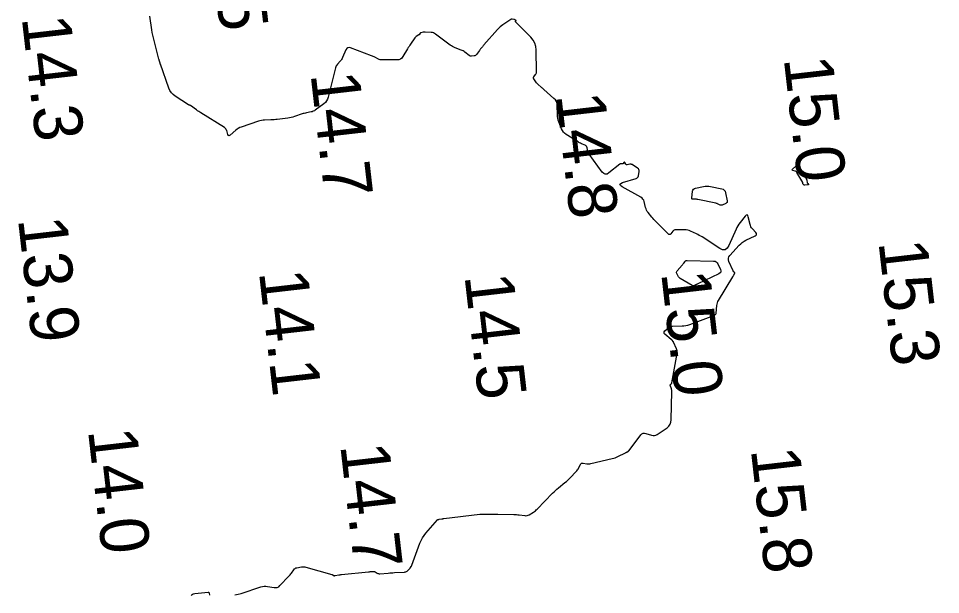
# Model space of a CAD drawing. Extents: x 1023796 to 1112670, y 656573 to 837340.
# Drawn here: x 1109831.6 to 1109926.4, y 680947.7 to 681006.9 of the extents above; entities that cross this region are included whole.
import ezdxf

# ---------------------------------------------------------------- set-up
doc = ezdxf.new("R2010")
doc.units = 0
doc.layers.add('V-CHAN-CONT-15FT', color=7, linetype='Continuous')
doc.layers.add('V-TOPO-SOUN', color=7, linetype='Continuous')

msp = doc.modelspace()

# ---------------------------------------------------------------- linework, layer by layer
at = {"layer": 'V-CHAN-CONT-15FT'}
for points in [[(1109853.897, 680947.649), (1109854.213, 680947.716), (1109854.525, 680947.805), (1109856.564, 680948.467), (1109856.731, 680948.51), (1109856.9, 680948.533), (1109857.07, 680948.536), (1109857.241, 680948.519), (1109857.931, 680948.407), (1109858.097, 680948.399), (1109858.25, 680948.429), (1109858.391, 680948.497), (1109858.518, 680948.604), (1109859.44, 680949.569), (1109859.511, 680949.646), (1109859.578, 680949.725), (1109859.641, 680949.808), (1109859.702, 680949.893), (1109859.936, 680950.239), (1109860, 680950.317), (1109860.075, 680950.378), (1109860.161, 680950.422), (1109860.258, 680950.449), (1109860.738, 680950.538), (1109860.851, 680950.552), (1109860.964, 680950.553), (1109861.077, 680950.541), (1109861.189, 680950.516), (1109863.848, 680949.753), (1109863.877, 680949.744), (1109863.905, 680949.733), (1109863.933, 680949.719), (1109863.959, 680949.704), (1109864.098, 680949.619), (1109864.107, 680949.615), (1109864.116, 680949.613), (1109864.125, 680949.613), (1109864.135, 680949.616), (1109864.173, 680949.632), (1109864.182, 680949.636), (1109864.192, 680949.639), (1109864.202, 680949.642), (1109864.212, 680949.644), (1109864.586, 680949.709), (1109864.652, 680949.719), (1109864.717, 680949.729), (1109864.784, 680949.738), (1109864.85, 680949.745), (1109867.625, 680950.027), (1109867.682, 680950.032), (1109867.738, 680950.038), (1109867.795, 680950.043), (1109867.852, 680950.049), (1109868.079, 680950.07), (1109868.134, 680950.071), (1109868.188, 680950.063), (1109868.24, 680950.047), (1109868.29, 680950.022), (1109868.528, 680949.882), (1109868.585, 680949.854), (1109868.644, 680949.835), (1109868.706, 680949.826), (1109868.77, 680949.827), (1109869.636, 680949.899), (1109869.802, 680949.913), (1109869.968, 680949.925), (1109870.134, 680949.936), (1109870.3, 680949.946), (1109871.337, 680950.004), (1109871.406, 680950.014), (1109871.47, 680950.034), (1109871.529, 680950.066), (1109871.584, 680950.108), (1109871.847, 680950.345), (1109871.873, 680950.37), (1109871.897, 680950.397), (1109871.919, 680950.426), (1109871.938, 680950.456), (1109872.014, 680950.58), (1109872.032, 680950.612), (1109872.048, 680950.644), (1109872.063, 680950.677), (1109872.077, 680950.711), (1109872.911, 680952.954), (1109873.03, 680953.236), (1109873.173, 680953.503), (1109873.34, 680953.757), (1109873.53, 680953.997), (1109874.721, 680955.37), (1109874.731, 680955.38), (1109874.743, 680955.389), (1109874.755, 680955.395), (1109874.769, 680955.4), (1109874.826, 680955.415), (1109874.841, 680955.418), (1109874.855, 680955.421), (1109874.87, 680955.424), (1109874.884, 680955.426), (1109875.158, 680955.466), (1109875.209, 680955.473), (1109875.259, 680955.48), (1109875.31, 680955.487), (1109875.36, 680955.493), (1109879.065, 680955.935), (1109879.142, 680955.943), (1109879.219, 680955.949), (1109879.296, 680955.952), (1109879.374, 680955.953), (1109879.683, 680955.951), (1109879.761, 680955.951), (1109879.838, 680955.951), (1109879.916, 680955.951), (1109879.993, 680955.952), (1109880.49, 680955.956), (1109880.598, 680955.957), (1109880.707, 680955.956), (1109880.816, 680955.955), (1109880.924, 680955.954), (1109882.566, 680955.921), (1109882.704, 680955.917), (1109882.841, 680955.908), (1109882.978, 680955.895), (1109883.115, 680955.878), (1109883.687, 680955.8), (1109883.808, 680955.793), (1109883.925, 680955.807), (1109884.039, 680955.841), (1109884.147, 680955.896), (1109884.574, 680956.155), (1109884.678, 680956.223), (1109884.778, 680956.297), (1109884.872, 680956.378), (1109884.961, 680956.465), (1109886.55, 680958.109), (1109886.694, 680958.253), (1109886.842, 680958.393), (1109886.995, 680958.528), (1109887.151, 680958.658), (1109887.817, 680959.195), (1109887.958, 680959.313), (1109888.096, 680959.435), (1109888.229, 680959.562), (1109888.359, 680959.693), (1109888.981, 680960.341), (1109889.05, 680960.418), (1109889.112, 680960.5), (1109889.168, 680960.586), (1109889.217, 680960.677), (1109889.407, 680961.06), (1109889.457, 680961.135), (1109889.521, 680961.183), (1109889.597, 680961.206), (1109889.688, 680961.202), (1109890.075, 680961.134), (1109890.172, 680961.122), (1109890.268, 680961.12), (1109890.364, 680961.127), (1109890.46, 680961.144), (1109892.67, 680961.654), (1109892.823, 680961.694), (1109892.974, 680961.743), (1109893.121, 680961.801), (1109893.264, 680961.867), (1109894.05, 680962.26), (1109894.084, 680962.277), (1109894.117, 680962.295), (1109894.15, 680962.314), (1109894.182, 680962.333), (1109894.311, 680962.41), (1109894.343, 680962.431), (1109894.371, 680962.454), (1109894.398, 680962.48), (1109894.421, 680962.509), (1109895.627, 680964.1), (1109895.73, 680964.205), (1109895.847, 680964.265), (1109895.977, 680964.282), (1109896.122, 680964.255), (1109896.727, 680964.058), (1109896.876, 680964.026), (1109897.02, 680964.029), (1109897.158, 680964.067), (1109897.292, 680964.14), (1109898.307, 680964.837), (1109898.493, 680964.998), (1109898.628, 680965.186), (1109898.711, 680965.402), (1109898.742, 680965.646), (1109898.801, 680968.565), (1109898.799, 680968.636), (1109898.79, 680968.706), (1109898.775, 680968.775), (1109898.753, 680968.842), (1109898.621, 680969.191), (1109898.615, 680969.216), (1109898.617, 680969.239), (1109898.628, 680969.259), (1109898.647, 680969.277), (1109898.738, 680969.343), (1109898.759, 680969.361), (1109898.775, 680969.382), (1109898.787, 680969.406), (1109898.794, 680969.432), (1109899.344, 680972.472), (1109899.357, 680972.596), (1109899.351, 680972.718), (1109899.327, 680972.837), (1109899.284, 680972.954), (1109898.973, 680973.636), (1109898.968, 680973.648), (1109898.963, 680973.661), (1109898.953, 680973.685), (1109898.95, 680973.691), (1109898.947, 680973.697), (1109898.944, 680973.702), (1109898.939, 680973.707), (1109898.825, 680973.834), (1109898.805, 680973.856), (1109898.783, 680973.877), (1109898.761, 680973.898), (1109898.737, 680973.918), (1109898.095, 680974.451), (1109898.023, 680974.531), (1109897.998, 680974.611), (1109898.019, 680974.693), (1109898.086, 680974.776), (1109898.447, 680975.111), (1109898.541, 680975.184), (1109898.643, 680975.237), (1109898.754, 680975.27), (1109898.873, 680975.283), (1109899.847, 680975.303), (1109900.049, 680975.316), (1109900.248, 680975.345), (1109900.444, 680975.39), (1109900.636, 680975.452), (1109902.848, 680976.268), (1109902.899, 680976.287), (1109902.95, 680976.309), (1109903, 680976.331), (1109903.05, 680976.355), (1109903.247, 680976.454), (1109903.291, 680976.482), (1109903.324, 680976.518), (1109903.346, 680976.561), (1109903.356, 680976.613), (1109903.431, 680977.379), (1109903.453, 680977.522), (1109903.491, 680977.661), (1109903.543, 680977.794), (1109903.611, 680977.922), (1109905.065, 680980.338), (1109905.09, 680980.38), (1109905.113, 680980.423), (1109905.136, 680980.467), (1109905.157, 680980.512), (1109905.261, 680980.743), (1109905.266, 680980.761), (1109905.265, 680980.777), (1109905.258, 680980.791), (1109905.244, 680980.803), (1109905.156, 680980.861), (1109905.149, 680980.867), (1109905.142, 680980.873), (1109905.136, 680980.881), (1109905.132, 680980.889), (1109905.111, 680980.933), (1109905.103, 680980.95), (1109905.099, 680980.959), (1109904.664, 680981.931), (1109904.614, 680982.093), (1109904.613, 680982.246), (1109904.662, 680982.391), (1109904.759, 680982.529), (1109905.721, 680983.591), (1109905.877, 680983.747), (1109906.046, 680983.886), (1109906.227, 680984.008), (1109906.421, 680984.112), (1109907.382, 680984.573), (1109907.476, 680984.636), (1109907.517, 680984.709), (1109907.506, 680984.792), (1109907.442, 680984.885), (1109907.081, 680985.279), (1109906.998, 680985.382), (1109906.93, 680985.492), (1109906.877, 680985.61), (1109906.839, 680985.736), (1109906.654, 680986.518), (1109906.604, 680986.653), (1109906.537, 680986.709), (1109906.452, 680986.686), (1109906.35, 680986.586), (1109905.822, 680985.916), (1109905.702, 680985.755), (1109905.594, 680985.587), (1109905.496, 680985.413), (1109905.408, 680985.232), (1109904.66, 680983.546), (1109904.487, 680983.272), (1109904.274, 680983.134), (1109904.02, 680983.132), (1109903.726, 680983.267), (1109901.908, 680984.437), (1109901.768, 680984.524), (1109901.625, 680984.607), (1109901.48, 680984.686), (1109901.332, 680984.76), (1109900.736, 680985.048), (1109900.585, 680985.111), (1109900.43, 680985.155), (1109900.27, 680985.181), (1109900.107, 680985.189), (1109899.185, 680985.181), (1109899.1, 680985.172), (1109899.024, 680985.145), (1109898.956, 680985.1), (1109898.898, 680985.037), (1109898.682, 680984.752), (1109898.627, 680984.698), (1109898.569, 680984.677), (1109898.509, 680984.69), (1109898.447, 680984.736), (1109897.146, 680986.032), (1109897.041, 680986.14), (1109896.939, 680986.25), (1109896.84, 680986.363), (1109896.744, 680986.479), (1109896.367, 680986.947), (1109896.28, 680987.068), (1109896.207, 680987.196), (1109896.149, 680987.331), (1109896.106, 680987.473), (1109895.958, 680988.071), (1109895.909, 680988.21), (1109895.836, 680988.331), (1109895.739, 680988.433), (1109895.619, 680988.518), (1109893.697, 680989.608), (1109893.52, 680989.737), (1109893.47, 680989.851), (1109893.545, 680989.951), (1109893.746, 680990.036), (1109895.119, 680990.44), (1109895.214, 680990.481), (1109895.288, 680990.542), (1109895.338, 680990.623), (1109895.367, 680990.723), (1109895.435, 680991.164), (1109895.438, 680991.268), (1109895.413, 680991.36), (1109895.362, 680991.439), (1109895.282, 680991.507), (1109894.727, 680991.871), (1109894.672, 680991.901), (1109894.615, 680991.918), (1109894.556, 680991.923), (1109894.495, 680991.916), (1109894.208, 680991.859), (1109894.166, 680991.856), (1109894.13, 680991.865), (1109894.098, 680991.885), (1109894.072, 680991.917), (1109893.963, 680992.087), (1109893.944, 680992.109), (1109893.925, 680992.117), (1109893.904, 680992.112), (1109893.883, 680992.094), (1109893.791, 680991.991), (1109893.77, 680991.971), (1109893.746, 680991.959), (1109893.719, 680991.952), (1109893.691, 680991.953), (1109893.57, 680991.967), (1109893.541, 680991.968), (1109893.513, 680991.963), (1109893.487, 680991.952), (1109893.463, 680991.936), (1109892.334, 680991.023), (1109892.143, 680990.91), (1109891.965, 680990.887), (1109891.798, 680990.954), (1109891.643, 680991.112), (1109890.295, 680992.948), (1109890.246, 680993.022), (1109890.207, 680993.1), (1109890.176, 680993.181), (1109890.154, 680993.267), (1109890.083, 680993.617), (1109890.058, 680993.698), (1109890.016, 680993.766), (1109889.958, 680993.821), (1109889.884, 680993.863), (1109889.505, 680994.027), (1109889.415, 680994.067), (1109889.327, 680994.111), (1109889.241, 680994.159), (1109889.157, 680994.21), (1109887.933, 680994.981), (1109887.781, 680995.094), (1109887.653, 680995.225), (1109887.547, 680995.377), (1109887.465, 680995.547), (1109887.184, 680996.267), (1109887.122, 680996.449), (1109887.077, 680996.634), (1109887.049, 680996.822), (1109887.038, 680997.013), (1109887.025, 680997.947), (1109887.001, 680998.157), (1109886.937, 680998.349), (1109886.832, 680998.522), (1109886.687, 680998.676), (1109885.637, 680999.591), (1109885.566, 680999.653), (1109885.496, 680999.716), (1109885.425, 680999.779), (1109885.355, 680999.842), (1109885.067, 681000.104), (1109885.003, 681000.165), (1109884.943, 681000.229), (1109884.886, 681000.296), (1109884.833, 681000.367), (1109884.608, 681000.685), (1109884.578, 681000.742), (1109884.569, 681000.798), (1109884.581, 681000.854), (1109884.615, 681000.909), (1109884.792, 681001.128), (1109884.83, 681001.184), (1109884.858, 681001.245), (1109884.874, 681001.309), (1109884.879, 681001.378), (1109884.862, 681003.656), (1109884.827, 681004.022), (1109884.725, 681004.362), (1109884.557, 681004.674), (1109884.324, 681004.959), (1109882.746, 681006.565), (1109882.738, 681006.576), (1109882.735, 681006.587), (1109882.737, 681006.598), (1109882.744, 681006.609), (1109882.781, 681006.655), (1109882.787, 681006.666), (1109882.788, 681006.677), (1109882.784, 681006.686), (1109882.774, 681006.694), (1109882.66, 681006.763), (1109882.636, 681006.776), (1109882.612, 681006.786), (1109882.586, 681006.794), (1109882.56, 681006.8), (1109882.381, 681006.826), (1109882.343, 681006.829), (1109882.306, 681006.824), (1109882.271, 681006.812), (1109882.238, 681006.794), (1109881.42, 681006.238), (1109881.277, 681006.134), (1109881.141, 681006.021), (1109881.013, 681005.9), (1109880.892, 681005.77), (1109879.493, 681004.17), (1109879.453, 681004.125), (1109879.413, 681004.079), (1109879.373, 681004.034), (1109879.333, 681003.988), (1109879.173, 681003.807), (1109879.133, 681003.761), (1109879.095, 681003.715), (1109879.058, 681003.667), (1109879.023, 681003.618), (1109878.711, 681003.183), (1109878.667, 681003.132), (1109878.616, 681003.093), (1109878.557, 681003.066), (1109878.491, 681003.051), (1109878.214, 681003.014), (1109878.146, 681003.012), (1109878.082, 681003.022), (1109878.022, 681003.046), (1109877.966, 681003.083), (1109877.537, 681003.426), (1109877.445, 681003.493), (1109877.349, 681003.553), (1109877.248, 681003.606), (1109877.143, 681003.65), (1109876.531, 681003.88), (1109876.396, 681003.937), (1109876.266, 681004.003), (1109876.141, 681004.077), (1109876.02, 681004.161), (1109874.509, 681005.299), (1109874.408, 681005.364), (1109874.302, 681005.412), (1109874.189, 681005.444), (1109874.07, 681005.458), (1109873.435, 681005.491), (1109873.387, 681005.492), (1109873.339, 681005.49), (1109873.291, 681005.485), (1109873.243, 681005.478), (1109873.016, 681005.434), (1109872.988, 681005.426), (1109872.964, 681005.413), (1109872.944, 681005.395), (1109872.927, 681005.373), (1109872.839, 681005.229), (1109872.837, 681005.226), (1109872.833, 681005.224), (1109872.829, 681005.223), (1109872.825, 681005.223), (1109872.807, 681005.226), (1109872.802, 681005.226), (1109872.798, 681005.225), (1109872.794, 681005.224), (1109872.79, 681005.222), (1109872.525, 681005.048), (1109872.482, 681005.016), (1109872.442, 681004.981), (1109872.406, 681004.942), (1109872.373, 681004.899), (1109871.945, 681004.267), (1109871.864, 681004.146), (1109871.786, 681004.024), (1109871.708, 681003.901), (1109871.633, 681003.776), (1109871.155, 681002.976), (1109871.038, 681002.823), (1109870.896, 681002.714), (1109870.73, 681002.65), (1109870.539, 681002.629), (1109869.004, 681002.639), (1109868.908, 681002.645), (1109868.814, 681002.662), (1109868.723, 681002.689), (1109868.635, 681002.728), (1109868.287, 681002.903), (1109868.199, 681002.946), (1109868.11, 681002.986), (1109868.02, 681003.024), (1109867.93, 681003.059), (1109865.776, 681003.863), (1109865.621, 681003.897), (1109865.489, 681003.875), (1109865.383, 681003.795), (1109865.3, 681003.659), (1109864.964, 681002.877), (1109864.916, 681002.778), (1109864.86, 681002.684), (1109864.796, 681002.595), (1109864.724, 681002.511), (1109864.421, 681002.187), (1109864.351, 681002.103), (1109864.294, 681002.012), (1109864.249, 681001.914), (1109864.216, 681001.81), (1109863.487, 680998.805), (1109863.419, 680998.601), (1109863.319, 680998.418), (1109863.189, 680998.256), (1109863.027, 680998.115), (1109862.153, 680997.473), (1109862.054, 680997.408), (1109861.949, 680997.356), (1109861.839, 680997.315), (1109861.724, 680997.287), (1109861.252, 680997.199), (1109861.135, 680997.175), (1109861.019, 680997.146), (1109860.903, 680997.114), (1109860.789, 680997.078), (1109860.022, 680996.817), (1109859.855, 680996.765), (1109859.686, 680996.721), (1109859.515, 680996.686), (1109859.343, 680996.66), (1109858.25, 680996.522), (1109858.088, 680996.503), (1109857.925, 680996.488), (1109857.762, 680996.476), (1109857.599, 680996.468), (1109856.946, 680996.442), (1109856.784, 680996.43), (1109856.623, 680996.406), (1109856.465, 680996.371), (1109856.309, 680996.325), (1109854.533, 680995.734), (1109854.382, 680995.676), (1109854.239, 680995.603), (1109854.105, 680995.515), (1109853.978, 680995.414), (1109853.404, 680994.903), (1109853.33, 680994.854), (1109853.268, 680994.848), (1109853.218, 680994.885), (1109853.179, 680994.964), (1109853.048, 680995.368), (1109853.008, 680995.463), (1109852.954, 680995.548), (1109852.886, 680995.621), (1109852.803, 680995.683), (1109850.398, 680997.199), (1109850.284, 680997.271), (1109850.172, 680997.345), (1109850.06, 680997.42), (1109849.949, 680997.497), (1109849.317, 680997.937), (1109849.302, 680997.947), (1109849.286, 680997.956), (1109849.269, 680997.963), (1109849.251, 680997.969), (1109849.18, 680997.99), (1109849.163, 680997.996), (1109849.146, 680998.003), (1109849.129, 680998.011), (1109849.114, 680998.021), (1109847.753, 680998.908), (1109847.539, 680999.073), (1109847.359, 680999.265), (1109847.214, 680999.484), (1109847.103, 680999.731), (1109846.227, 681002.184), (1109846.218, 681002.21), (1109846.21, 681002.236), (1109846.202, 681002.263), (1109846.196, 681002.29), (1109846.171, 681002.398), (1109846.164, 681002.425), (1109846.157, 681002.452), (1109846.15, 681002.479), (1109846.143, 681002.506), (1109846.112, 681002.615), (1109846.104, 681002.642), (1109846.096, 681002.669), (1109846.089, 681002.696), (1109846.082, 681002.723), (1109845.575, 681004.635), (1109845.506, 681004.908), (1109845.446, 681005.183), (1109845.394, 681005.46), (1109845.351, 681005.738), (1109845.153, 681007.128)], [(1109849.38, 680947.596), (1109849.486, 680947.695), (1109849.615, 680947.76), (1109849.768, 680947.792), (1109851.125, 680947.92), (1109851.17, 680947.918), (1109851.205, 680947.902), (1109851.229, 680947.873), (1109851.243, 680947.83), (1109851.278, 680947.633)]]:
    msp.add_lwpolyline(points, dxfattribs=at)
for points in [[(1109911.182, 680991.321), (1109911.187, 680991.353), (1109911.216, 680991.391), (1109911.553, 680991.722), (1109911.596, 680991.754), (1109911.64, 680991.766), (1109911.685, 680991.757), (1109911.731, 680991.729), (1109911.915, 680991.576), (1109911.959, 680991.536), (1109911.999, 680991.492), (1109912.035, 680991.445), (1109912.067, 680991.395), (1109912.638, 680990.396), (1109912.658, 680990.358), (1109912.674, 680990.317), (1109912.686, 680990.276), (1109912.694, 680990.233), (1109912.721, 680990.026), (1109912.727, 680989.999), (1109912.736, 680989.974), (1109912.748, 680989.95), (1109912.764, 680989.928), (1109912.836, 680989.841), (1109912.848, 680989.822), (1109912.849, 680989.807), (1109912.838, 680989.797), (1109912.816, 680989.792), (1109912.488, 680989.756), (1109912.458, 680989.756), (1109912.431, 680989.762), (1109912.407, 680989.775), (1109912.385, 680989.795), (1109912.272, 680989.916), (1109912.266, 680989.923), (1109912.262, 680989.931), (1109912.26, 680989.94), (1109912.259, 680989.949), (1109912.259, 680989.986), (1109912.258, 680989.995), (1109912.257, 680990.004), (1109912.254, 680990.013), (1109912.25, 680990.021), (1109911.642, 680991.082), (1109911.61, 680991.129), (1109911.57, 680991.166), (1109911.524, 680991.195), (1109911.471, 680991.215), (1109911.246, 680991.277), (1109911.202, 680991.296)], [(1109904.195, 680989.251), (1109904.278, 680989.132), (1109904.328, 680988.979), (1109904.491, 680988.14), (1109904.496, 680988.059), (1109904.476, 680987.99), (1109904.432, 680987.934), (1109904.363, 680987.891), (1109903.983, 680987.719), (1109903.93, 680987.701), (1109903.876, 680987.695), (1109903.823, 680987.702), (1109903.769, 680987.721), (1109903.556, 680987.824), (1109903.503, 680987.848), (1109903.448, 680987.869), (1109903.392, 680987.886), (1109903.334, 680987.9), (1109901.467, 680988.295), (1109901.404, 680988.306), (1109901.341, 680988.315), (1109901.277, 680988.319), (1109901.214, 680988.32), (1109900.958, 680988.318), (1109900.903, 680988.326), (1109900.866, 680988.349), (1109900.847, 680988.389), (1109900.847, 680988.444), (1109900.939, 680989.133), (1109900.971, 680989.256), (1109901.033, 680989.351), (1109901.124, 680989.42), (1109901.244, 680989.461), (1109902.057, 680989.632), (1109902.237, 680989.66), (1109902.417, 680989.67), (1109902.598, 680989.66), (1109902.778, 680989.631), (1109903.926, 680989.389), (1109904.077, 680989.336)], [(1109899.293, 680980.826), (1109899.313, 680980.89), (1109899.354, 680980.951), (1109899.86, 680981.534), (1109899.902, 680981.582), (1109899.943, 680981.631), (1109899.982, 680981.681), (1109900.021, 680981.732), (1109900.176, 680981.935), (1109900.217, 680981.98), (1109900.265, 680982.011), (1109900.32, 680982.029), (1109900.381, 680982.034), (1109903.096, 680981.961), (1109903.243, 680981.939), (1109903.366, 680981.882), (1109903.466, 680981.791), (1109903.542, 680981.664), (1109903.801, 680981.086), (1109903.839, 680980.951), (1109903.826, 680980.836), (1109903.761, 680980.739), (1109903.645, 680980.661), (1109901.479, 680979.625), (1109901.43, 680979.601), (1109901.38, 680979.577), (1109901.331, 680979.552), (1109901.281, 680979.528), (1109901.084, 680979.429), (1109901.035, 680979.411), (1109900.987, 680979.407), (1109900.939, 680979.415), (1109900.891, 680979.437), (1109899.658, 680980.18), (1109899.595, 680980.225), (1109899.54, 680980.277), (1109899.493, 680980.337), (1109899.455, 680980.404), (1109899.318, 680980.689), (1109899.295, 680980.759)]]:
    msp.add_lwpolyline(points, close=True, dxfattribs=at)

# ---------------------------------------------------------------- texts
at = {"layer": 'V-TOPO-SOUN'}
for s, p in [('15.5 ', (1109850.93, 681018.35)), ('14.3 ', (1109831.971, 681006.993)), ('15.0 ', (1109910.298, 681002.791)), ('14.7 ', (1109861.661, 681001.183)), ('14.8 ', (1109886.891, 680999.053)), ('13.9 ', (1109831.581, 680986.293)), ('15.3 ', (1109920.031, 680983.923)), ('14.1 ', (1109856.352, 680980.843)), ('14.5 ', (1109877.48, 680980.46)), ('15.0 ', (1109897.698, 680980.741)), ('14.0 ', (1109838.778, 680964.571)), ('14.7 ', (1109864.711, 680963.033)), ('15.8 ', (1109906.911, 680962.603))]:
    msp.add_text(s, height=5, rotation=276.55942, dxfattribs=at).set_placement(p)

doc.saveas('drawing.dxf')
